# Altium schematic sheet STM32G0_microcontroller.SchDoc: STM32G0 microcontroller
size A4; Date: Not used; ApprovedBy: Not used; CheckedBy: Not used; Author: Not used; CompanyName: STMicroelectronics; DrawnBy: Not used; Engineer: Not used; Organization: Not used; Address1: Not used; Address2: Not used; Address3: Not used; Address4: Not used; DocumentNumber: Not used; Revision: Not used; SheetNumber: 3; SheetTotal: 6
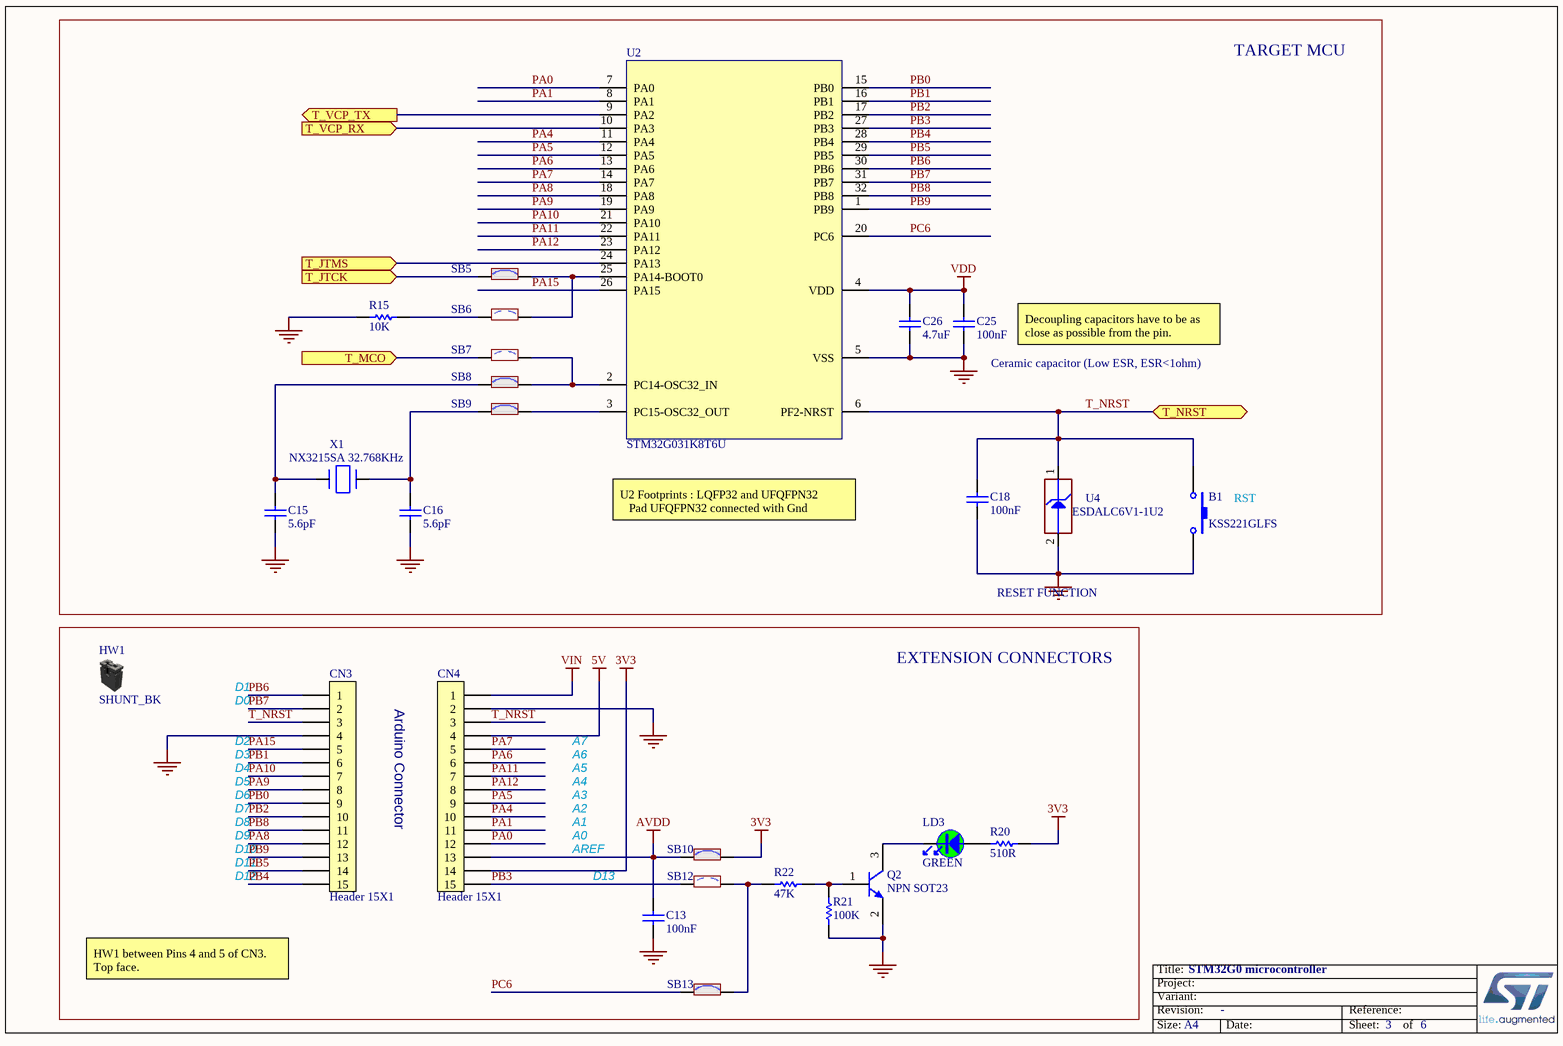
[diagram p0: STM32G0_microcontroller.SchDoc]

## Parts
B1  value KSS221GLFS  [SWI_C&K_ITT_KSS221G]  (hidden comment: SW-PB)
C13  value 100nF  [C0402]  (hidden comment: Capacitor)
C15  value 5.6pF  [C0402]  (hidden comment: Capacitor)
C16  value 5.6pF  [C0402]  (hidden comment: Capacitor)
C18  value 100nF  [C0402]  (hidden comment: Capacitor)
C25  value 100nF  [C0402]  (hidden comment: Capacitor)
C26  value 4.7uF  [C0402]  (hidden comment: Capacitor)
CN3  Header 15x1  [CON_LYCN_313115S161145]
CN4  Header 15x1  [CON_LYCN_313115S161145]
HW1  value SHUNT_BK  (hidden comment: Shunt Black 2.54mm)  (mechanical)
LD3  value GREEN  [LED_0603_GREEN]  (hidden comment: LED_green)
Q2  value NPN SOT23  [NPN_SOT23]  (hidden comment: 9013-SOT23)
R15  value 10K  [R0402]  (hidden comment: Resistor)
R20  value 510R  [R0402]  (hidden comment: Resistor)
R21  value 100K  [R0402]  (hidden comment: Resistor)
R22  value 47K  [R0402]  (hidden comment: Resistor)
SB5  SB_ON  [SOLDER-BRIDGE_R0603-0R]  (value not drawn)
SB6  SB_OFF  [SOLDER-BRIDGE_R0603-0R]  (value not drawn)
SB7  SB_OFF  [SOLDER-BRIDGE_R0603-0R]  (value not drawn)
SB8  SB_ON  [SOLDER-BRIDGE_R0603-0R]  (value not drawn)
SB9  SB_ON  [SOLDER-BRIDGE_R0603-0R]  (value not drawn)
SB10  SB_ON  [SOLDER-BRIDGE_R0603-0R]  (value not drawn)
SB12  SB_OFF  [SOLDER-BRIDGE_R0603-0R]  (value not drawn)
SB13  SB_ON  [SOLDER-BRIDGE_R0603-0R]  (value not drawn)
U2  STM32G031K8T6U  [ICC_LQFP32_7X7_P080__UFQFPN32-EPAD_5X5_P050__DI]
U4  value ESDALC6V1-1U2  [ESD_ST0201]  (hidden comment: ESD-TRANSIL)
X1  value NX3215SA 32.768KHz  [CRY_NX3215SA_2P]  (hidden comment: XTAL_2_PINS)

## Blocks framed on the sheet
TARGET MCU: B1 C15 C16 C18 C25 C26 R15 SB5-SB9 U2 U4 X1
EXTENSION CONNECTORS: C13 CN3 CN4 HW1 LD3 Q2 R20-R22 SB10 SB12 SB13

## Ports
T_JTCK (in), T_JTMS (in), T_MCO (in), T_NRST (bidir), T_VCP_RX (in), T_VCP_TX (out)

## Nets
3V3: CN4.14 R20.2 SB10.2
5V: CN4.4
AVDD: C13.2 CN4.13 SB10.1
GND: B1.2 C13.1 C15.1 C16.1 C18.1 C25.1 C26.1 CN3.4 CN4.2 Q2.2(E) R15.1 R21.1 U2.5(VSS) U4.2(GND)
VDD: C25.2 C26.2 U2.4(VDD)
VIN: CN4.1
PA0: CN4.12 U2.7(PA0)
PA1: CN4.11 U2.8(PA1)
PA4: CN4.10 U2.11(PA4)
PA5: CN4.9 U2.12(PA5)
PA6: CN4.6 U2.13(PA6)
PA7: CN4.5 U2.14(PA7)
PA8: CN3.12 U2.18(PA8)
PA9: CN3.8 U2.19(PA9)
PA10: CN3.7 U2.21(PA10)
PA11: CN4.7 U2.22(PA11)
PA12: CN4.8 U2.23(PA12)
PA15: CN3.5 U2.26(PA15)
PB0: CN3.9 U2.15(PB0)
PB1: CN3.6 U2.16(PB1)
PB2: CN3.10 U2.17(PB2)
PB3: CN4.15 SB12.1 U2.27(PB3)
PB4: CN3.15 U2.28(PB4)
PB5: CN3.14 U2.29(PB5)
PB6: CN3.1 U2.30(PB6)
PB7: CN3.2 U2.31(PB7)
PB8: CN3.11 U2.32(PB8)
PB9: CN3.13 U2.1(PB9)
PC6: SB13.1 U2.20(PC6)
T_JTCK: SB5.1 ; port T_JTCK
T_JTMS: U2.24(PA13) ; port T_JTMS
T_MCO: SB7.1 ; port T_MCO
T_NRST: B1.1 C18.2 CN3.3 CN4.3 U2.6(PF2-NRST) U4.1(IO1) ; port T_NRST
T_VCP_RX: U2.10(PA3) ; port T_VCP_RX
T_VCP_TX: U2.9(PA2) ; port T_VCP_TX
NetC15_2: C15.2 SB8.1 X1.1(X1)
NetC16_2: C16.2 SB9.1 X1.2(X2)
NetLD3_1: LD3.1 R20.1
NetLD3_2: LD3.2 Q2.3(C)
NetQ2_1: Q2.1(B) R21.2 R22.2
NetR15_2: R15.2 SB6.1
NetR22_1: R22.1 SB12.2 SB13.2
NetSB5_2: SB5.2 SB6.2 U2.25(PA14-BOOT0)
NetSB7_2: SB7.2 SB8.2 U2.2(PC14-OSC32_IN)
NetSB9_2: SB9.2 U2.3(PC15-OSC32_OUT)

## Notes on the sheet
- (near C25) Ceramic capacitor (Low ESR, ESR<1ohm)
- Decoupling capacitors have to be as close as possible from the pin.
- U2 Footprints : LQFP32 and UFQFPN32
  Pad UFQFPN32 connected with Gnd
- (near B1) RST
- RESET FUNCTION
- D0
- D1
- Arduino Connector
- D2
- D4
- D3
- D5
- A4
- A5
- A6
- A7
- D6
- D7
- D8
- D9
- D10
- A0
- A1
- A2
- A3
- AREF
- D12
- D11
- D13
- HW1 between Pins 4 and 5 of CN3. Top face.

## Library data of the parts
B1 = MCD-01335: Subminiature Side Actuated Tact Switch for SMT - KSS series - 2.0 Newtons - Gull wing, SPST; Part_Type: Misc; Manufacturer: C&K; Provided_By: SUBCO; ECCN_US: EAR99; ECCN_EU: NEC
C13 C18 C25 = MCD-00102: Capacitor, MLCC, 100nF, 16V, X7R, 10%, 0402, T=0,5mm; Manufacturer_Part_Number: CC0402KRX7R7BB104; Manufacturer: YAGEO; Alternate_Manufacturer_Part_Number: GCM155R71C104KA55D; Alternate_Manufacturer: MURATA; Provided_By: SUBCO; ECCN_US: EAR99; ECCN_EU: NEC
C15 C16 = MCD-01374: Capacitor, MLCC, 5.6pF, 50V, NPO, +/- 0.1pF, 0402, T=0,5mm; Manufacturer_Part_Number: CC0402BRNPO9BN5R6; Manufacturer: YAGEO; Provided_By: SUBCO
C26 = MCD-00096: Capacitor, MLCC, 4.7uF, 6V3, X5R, 20%, 0402, T=0,5mm; Manufacturer_Part_Number: GRM155R60J475ME87; Manufacturer: MURATA; Provided_By: SUBCO; ECCN_US: EAR99; ECCN_EU: NEC
CN3 CN4 = MCD-01332: Pin header, 15x1, 2,54mm, VR, TH, Height 6mm/6mm; Part_Type: Connector; Manufacturer_Part_Number: 313115S161145; Manufacturer: LYCONN; Alternate_Manufacturer_Part_Number: TSW 115-08-F-S; Alternate_Manufacturer: SAMTEC; Provided_By: SUBCO
HW1 = MCD-00122: SHUNT, 2.54mm, height 6.10mm, BLACK; Part_Type: Misc; Manufacturer_Part_Number: SNT-100-BK-G; Manufacturer: SAMTEC; Alternate_Manufacturer_Part_Number: MJ-6B2.0*3.5; Alternate_Manufacturer: LIANYI; Provided_By: SUBCO; ECCN_US: EAR99; ECCN_EU: NEC
LD3 = MCD-00050: LED, Green, 0603; Manufacturer_Part_Number: 19-213SYGC/S530-E2/TR8; Manufacturer: EVERLIGHT; Part_Type: Display; Provided_By: SUBCO; ECCN_US: EAR99; ECCN_EU: NEC
Q2 = MCD-00073: NPN Bipolar Transistor; Part_Type: IC; Manufacturer_Part_Number: BSR14; Manufacturer: ON SEMICONDUCTOR; Alternate_Manufacturer_Part_Number: MMBT2222LT1G / MMBT2222ALT1G / MMBT2222ALT3G; Provided_By: SUBCO; ECCN_US: EAR99; ECCN_EU: NEC
R15 = MCD-00053: Resistor,10K,0402,1%,1/16W; Manufacturer_Part_Number: RC0402FR-0710KL; Manufacturer: YAGEO; Provided_By: SUBCO; ECCN_US: EAR99; ECCN_EU: NEC
R20 = MCD-00064: Resistor,510R,0402,1%,1/16W; Manufacturer_Part_Number: RC0402FR-07510RL; Manufacturer: YAGEO; Provided_By: SUBCO; ECCN_US: EAR99; ECCN_EU: NEC
R21 = MCD-00059: Resistor,100K,0402,1%,1/16W; Manufacturer_Part_Number: RC0402FR-07100KL; Manufacturer: YAGEO; Alternate_Manufacturer_Part_Number: RT0402FRE07100KL; Provided_By: SUBCO; ECCN_US: EAR99; ECCN_EU: NEC
R22 = MCD-00063: Resistor,47K,0402,1%,1/16W; Manufacturer_Part_Number: RC0402FR-0747KL; Manufacturer: YAGEO; Provided_By: SUBCO; ECCN_US: EAR99; ECCN_EU: NEC
SB5 SB8-SB10 SB13 = MCD-00071: Solder Bridge ON; Part_Type: Mechanical; Manufacturer_Part_Number: RC0603JR-070RL; Manufacturer: YAGEO; Provided_By: SUBCO
SB6 SB7 SB12 = MCD-00072: Solder Bridge OFF; Part_Type: Mechanical; Manufacturer_Part_Number: RC0603JR-070RL; Manufacturer: YAGEO; Provided_By: SUBCO
U2 = MCD-01738: Mainstream Arm Cortex-M0+ MCU with 64 Kbytes of of Flash memory memory, 8 Kbytes RAM, 64 MHz CPU, 2x USART, timers, ADC, comm. I/F, 1.65-3.6V; Manufacturer: STMICROELECTRONICS; Part_Type: IC; Provided_By: SUBCO with ST control; ECCN_US: 3A991A2; ECCN_EU: NEC
U4 = MCD-00170: ESD protection 6V1; Part_Type: Diode; Manufacturer: STMICROELECTRONICS; BMS_Part_Number: 9151132; Provided_By: SUBCO with ST control; ECCN_US: EAR99; ECCN_EU: NEC
X1 = MCD-00091: Crystal 32.768kHz, 6pF, +-20ppm, 50Kohms max, SMD; Part_Type: Crystal_Osc; Manufacturer_Part_Number: NX3215SA 32.768KHz EXS00A-MU00525; Manufacturer: NDK; BMS_Part_Number: 9157034; ECCN_US: EAR99; ECCN_EU: NEC; Provided_By: SUBCO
